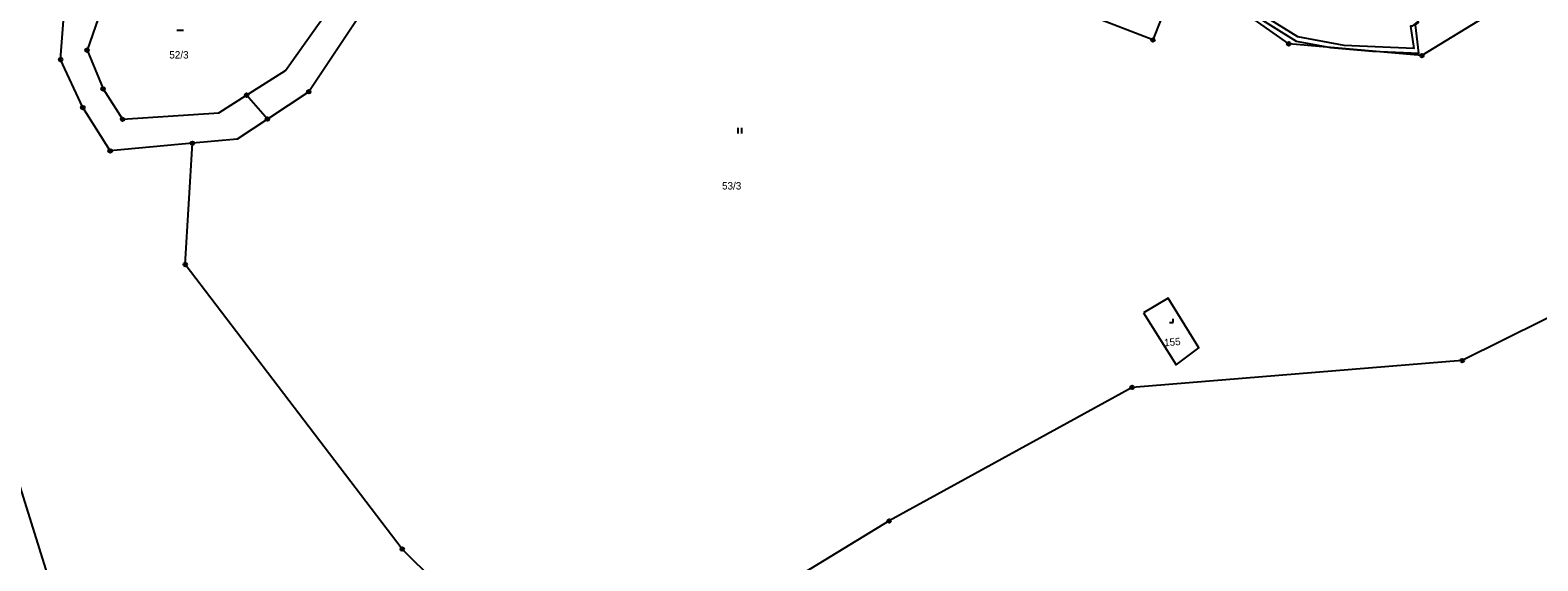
# Model space of a CAD drawing. Extents: x -745926 to -742978, y -968282 to -965689.
# Drawn here: x -743961.6 to -743757.5, y -967371.6 to -967299.8 of the extents above; entities that cross this region are included whole.
import ezdxf

# ---------------------------------------------------------------- set-up
doc = ezdxf.new("R2010")
doc.units = 0
for name, color, linetype in [('Hranice parcel', 7, 'Continuous'), ('Parcelní čísla', 7, 'Continuous'), ('Věcná břemena k části', 7, 'Continuous'), ('Značky bodu BP', 7, 'Continuous'), ('Značky kultur', 7, 'Continuous')]:
    doc.layers.add(name, color=color, linetype=linetype)

msp = doc.modelspace()

# ---------------------------------------------------------------- linework, layer by layer
at = {"layer": 'Hranice parcel'}
for p, q in [((-743809.64, -967301.14), (-743866.31, -967279.05)), ((-743805.97, -967291.84), (-743809.64, -967301.14)), ((-743929.51, -967311.85), (-743932.33, -967308.61))]:
    msp.add_line(p, q, dxfattribs=at)
for points in [[(-743934.64, -967274.82), (-743949.04, -967288.44), (-743953.91, -967302.52), (-743951.74, -967307.77), (-743949.11, -967311.88), (-743936.09, -967311.01), (-743932.33, -967308.61)], [(-743911.43, -967280.04), (-743912.34, -967287.71), (-743917.04, -967297.87), (-743923.9, -967308.15), (-743929.51, -967311.85)], [(-743932.33, -967308.61), (-743927.07, -967305.25), (-743920.04, -967295.37), (-743918, -967288.57)], [(-743939.65, -967315.12), (-743950.79, -967316.15), (-743954.49, -967310.29), (-743957.49, -967303.79), (-743956.48, -967290.29)], [(-743754.93, -967292), (-743773.22, -967303.26), (-743791.24, -967301.66), (-743799.74, -967295.65), (-743805.97, -967291.84)], [(-743984.68, -967297.06), (-743969.73, -967340.16), (-743958.46, -967376.2), (-743942.06, -967444.63), (-743937.6, -967458.75)], [(-743929.51, -967311.85), (-743933.62, -967314.56), (-743939.65, -967315.12)], [(-743729.02, -967325.29), (-743767.76, -967344.54), (-743812.45, -967348.17), (-743845.36, -967366.25), (-743888.51, -967392.58), (-743911.25, -967370.05), (-743940.62, -967331.53), (-743939.65, -967315.12)], [(-743810.92, -967338.08), (-743806.5, -967345.1), (-743803.4, -967342.83), (-743807.59, -967336.1), (-743810.92, -967338.08)]]:
    msp.add_lwpolyline(points, dxfattribs=at)
at = {"layer": 'Věcná břemena k části'}
msp.add_lwpolyline([(-743779.92, -967302.66), (-743773.63, -967302.93), (-743774.1, -967299.11), (-743773.67, -967298.77), (-743773.78, -967298.62), (-743774.56, -967299.28), (-743774.77, -967299.26), (-743774.31, -967302.31), (-743783.74, -967301.9), (-743790.04, -967300.71), (-743798.92, -967295.18), (-743804.82, -967291.12), (-743805.11, -967286.25), (-743807.54, -967285.23), (-743805.69, -967286.57), (-743805.4, -967291.44), (-743799.24, -967295.68), (-743790.26, -967301.28), (-743785.6, -967302.16)], close=True, dxfattribs=at)
at = {"layer": 'Značky bodu BP'}
for centre, radius in [((-743953.91, -967302.52), 0.25), ((-743953.91, -967302.52), 0.0152), ((-743809.64, -967301.14), 0.25), ((-743809.64, -967301.14), 0.0152), ((-743791.24, -967301.66), 0.25), ((-743791.24, -967301.66), 0.0152), ((-743957.49, -967303.79), 0.25), ((-743957.49, -967303.79), 0.0152), ((-743773.22, -967303.26), 0.25), ((-743773.22, -967303.26), 0.0152), ((-743951.74, -967307.77), 0.25), ((-743951.74, -967307.77), 0.0152), ((-743932.33, -967308.61), 0.25), ((-743932.33, -967308.61), 0.0152), ((-743923.9, -967308.15), 0.25), ((-743923.9, -967308.15), 0.0152), ((-743954.49, -967310.29), 0.25), ((-743954.49, -967310.29), 0.0152), ((-743949.11, -967311.88), 0.25), ((-743949.11, -967311.88), 0.0152), ((-743929.51, -967311.85), 0.25), ((-743929.51, -967311.85), 0.0152), ((-743939.65, -967315.12), 0.25), ((-743939.65, -967315.12), 0.0152), ((-743950.79, -967316.15), 0.25), ((-743950.79, -967316.15), 0.0152), ((-743940.62, -967331.53), 0.25), ((-743940.62, -967331.53), 0.0152), ((-743767.76, -967344.54), 0.25), ((-743767.76, -967344.54), 0.0152), ((-743812.45, -967348.17), 0.25), ((-743812.45, -967348.17), 0.0152), ((-743845.36, -967366.25), 0.25), ((-743845.36, -967366.25), 0.0152), ((-743911.25, -967370.05), 0.25), ((-743911.25, -967370.05), 0.0152)]:
    msp.add_circle(centre, radius, dxfattribs=at)
at = {"layer": 'Značky kultur'}
for p, q in [((-743941.75, -967299.81), (-743940.87, -967299.81)), ((-743865.77, -967313.79), (-743865.77, -967313.04)), ((-743865.27, -967313.79), (-743865.27, -967313.04)), ((-743807.38, -967339.38), (-743806.88, -967339.38)), ((-743806.88, -967339.38), (-743806.88, -967338.88))]:
    msp.add_line(p, q, dxfattribs=at)

# ---------------------------------------------------------------- texts
at = {"layer": 'Parcelní čísla'}
for s, p in [('52/3', (-743942.78, -967303.65)), ('53/3', (-743867.96, -967321.38))]:
    msp.add_text(s, height=1, dxfattribs=at).set_placement(p)
msp.add_text('155', height=1, rotation=5, dxfattribs=at).set_placement((-743808.08, -967342.62))

doc.saveas('drawing.dxf')
